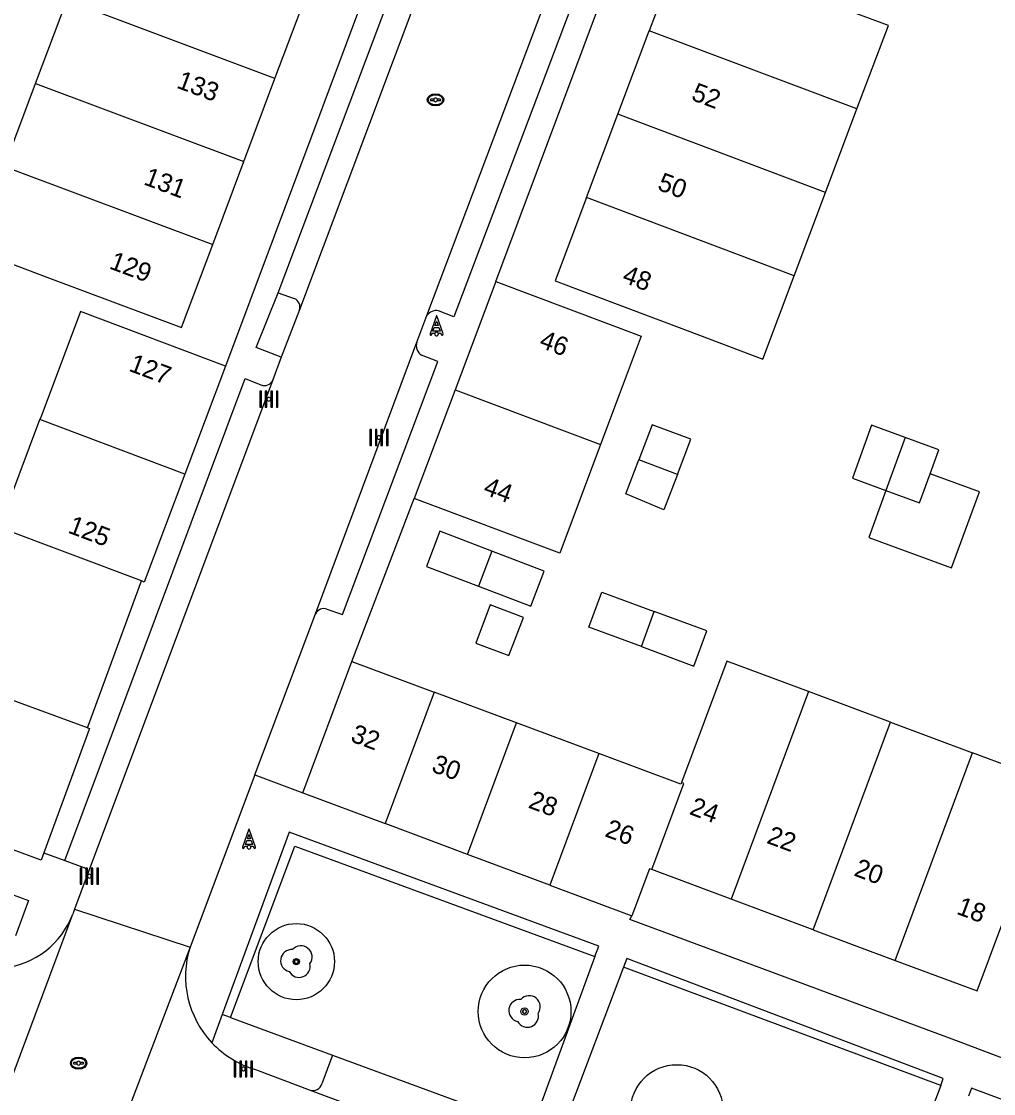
# Model space of a CAD drawing. Extents: x 192664 to 192925, y 446334 to 446521.
# Drawn here: x 192737.6 to 192789.9, y 446395.7 to 446453.5 of the extents above; entities that cross this region are included whole.
import ezdxf

# ---------------------------------------------------------------- set-up
doc = ezdxf.new("R2010")
doc.units = 0
for name, color, linetype in [('( Toegevoegd 29-11-2021 14_41_42) ondersteunend wegdeel vlak', 7, 'Continuous'), ('( Toegevoegd 29-11-2021 14_41_42) wegdeel vlak', 7, 'Continuous'), ('B-GV-GR-BOOM-S', 7, 'Continuous'), ('boom', 7, 'Continuous'), ('bovenleidingmast', 7, 'Continuous'), ('huisnummerreeks BGT', 7, 'Continuous'), ('inspectie-   rioolput', 7, 'Continuous'), ('kant open verharding', 7, 'Continuous'), ('kant verharding', 7, 'Continuous'), ('kolk', 7, 'Continuous'), ('Luifel', 7, 'Continuous'), ('pand op maaiveld vlak', 7, 'Continuous'), ('verkeerseiland - berm', 7, 'Continuous')]:
    doc.layers.add(name, color=color, linetype=linetype)

msp = doc.modelspace()

# ---------------------------------------------------------------- linework, layer by layer
at = {"layer": '( Toegevoegd 29-11-2021 14_41_42) ondersteunend wegdeel vlak'}
for p, q in [((192748.388, 446399.963), (192747.829, 446398.443)), ((192748.841, 446399.796), (192748.388, 446399.963)), ((192754.334, 446397.778), (192753.763, 446396.222)), ((192750.175, 446396.992), (192753.133, 446395.89))]:
    msp.add_line(p, q, dxfattribs=at)
for centre, radius, start, end in [((192751.82, 446402.274), 5.532, 223.8263, 252.70015), ((192753.27, 446396.393), 0.522, 254.72926, 340.84778)]:
    msp.add_arc(centre, radius, start, end, dxfattribs=at)
at = {"layer": '( Toegevoegd 29-11-2021 14_41_42) wegdeel vlak'}
for p, q in [((192750.151, 446412.873), (192746.655, 446403.591)), ((192740.44, 446405.64), (192740.343, 446405.376))]:
    msp.add_line(p, q, dxfattribs=at)
for points in [[(192768.471, 446403.091), (192768.677, 446403.651), (192751.996, 446409.781), (192748.388, 446399.963)], [(192807.071, 446391.618), (192806.989, 446391.38), (192789.199, 446398.084), (192788.212, 446398.449), (192770.35, 446405.075), (192770.467, 446405.283)], [(192787.1, 446396.135), (192787.242, 446396.51), (192770.185, 446402.974), (192770.009, 446402.51)], [(192806.008, 446389.049), (192806.18, 446389.51), (192788.76, 446395.99), (192788.604, 446395.572)]]:
    msp.add_lwpolyline(points, dxfattribs=at)
msp.add_arc((192751.656, 446402.024), 5.241, 162.6006, 223.09258, dxfattribs=at)
at = {"layer": 'B-GV-GR-BOOM-S'}
for centre, radius in [((192752.383, 446402.813), 2.054), ((192752.383, 446402.813), 0.164), ((192764.68, 446400.127), 2.5), ((192764.68, 446400.127), 0.2), ((192772.885, 446394.761), 2.5)]:
    msp.add_circle(centre, radius, dxfattribs=at)
at = {"layer": 'boom'}
for centre in [(192752.383, 446402.813), (192764.68, 446400.127)]:
    msp.add_circle(centre, 0.1, dxfattribs=at)
for centre, radius, start, end in [((192752.633, 446403.063), 0.6, 323.54458, 138.4658), ((192752.133, 446402.863), 0.6, 85.13702, 257.75442), ((192752.533, 446402.563), 0.6, 208.50578, 13.83556), ((192752.383, 446402.813), 0.1, 0, 180), ((192752.383, 446402.813), 0.1, 180, 0), ((192764.43, 446400.177), 0.6, 85.13702, 257.75442), ((192764.93, 446400.377), 0.6, 323.54458, 138.4658), ((192764.68, 446400.127), 0.1, 0, 180), ((192764.68, 446400.127), 0.1, 180, 0), ((192764.83, 446399.877), 0.6, 208.50578, 13.83556)]:
    msp.add_arc(centre, radius, start, end, dxfattribs=at)
at = {"layer": 'bovenleidingmast'}
for p, q in [((192759.928, 446437.605), (192759.587, 446436.632)), ((192760.287, 446436.632), (192759.946, 446437.605)), ((192749.824, 446409.954), (192749.483, 446408.981)), ((192750.183, 446408.981), (192749.842, 446409.954))]:
    msp.add_line(p, q, dxfattribs=at)
for points in [[(192759.946, 446437.302), (192760.024, 446437.082), (192759.85, 446437.082), (192759.928, 446437.302)], [(192759.681, 446436.599), (192759.71, 446436.682), (192759.85, 446436.682)], [(192760.024, 446436.682), (192760.164, 446436.682), (192760.193, 446436.599)], [(192749.842, 446409.651), (192749.92, 446409.431), (192749.746, 446409.431), (192749.824, 446409.651)], [(192749.577, 446408.948), (192749.606, 446409.031), (192749.746, 446409.031)], [(192749.92, 446409.031), (192750.06, 446409.031), (192750.089, 446408.948)]]:
    msp.add_lwpolyline(points, dxfattribs=at)
for points in [[(192760.059, 446436.982), (192760.129, 446436.782), (192759.745, 446436.782), (192759.815, 446436.982)], [(192749.955, 446409.331), (192750.025, 446409.131), (192749.641, 446409.131), (192749.711, 446409.331)]]:
    msp.add_lwpolyline(points, close=True, dxfattribs=at)
for centre, radius, start, end in [((192759.937, 446437.602), 0.01, 19.29005, 160.70995), ((192759.937, 446437.299), 0.01, 19.29005, 160.70995), ((192759.634, 446436.615), 0.05, 160.70995, 340.70995), ((192759.937, 446436.632), 0.1, 0, 180), ((192759.937, 446436.632), 0.1, 180, 0), ((192759.937, 446436.632), 0.1, 30, 150), ((192760.24, 446436.615), 0.05, 199.29005, 19.29005), ((192749.833, 446409.951), 0.01, 19.29005, 160.70995), ((192749.833, 446409.648), 0.01, 19.29005, 160.70995), ((192749.53, 446408.964), 0.05, 160.70995, 340.70995), ((192749.833, 446408.981), 0.1, 0, 180), ((192749.833, 446408.981), 0.1, 180, 0), ((192749.833, 446408.981), 0.1, 30, 150), ((192750.136, 446408.964), 0.05, 199.29005, 19.29005)]:
    msp.add_arc(centre, radius, start, end, dxfattribs=at)
at = {"layer": 'inspectie-   rioolput'}
for p, q in [((192759.79, 446449.284), (192759.633, 446449.284)), ((192759.633, 446449.209), (192759.79, 446449.209)), ((192760.133, 446449.284), (192759.976, 446449.284)), ((192759.976, 446449.209), (192760.133, 446449.209)), ((192740.56, 446397.379), (192740.403, 446397.379)), ((192740.403, 446397.305), (192740.56, 446397.305)), ((192740.903, 446397.379), (192740.746, 446397.379)), ((192740.746, 446397.305), (192740.903, 446397.305))]:
    msp.add_line(p, q, dxfattribs=at)
for centre, radius, start, end in [((192759.633, 446449.246), 0.0375, 90, 270), ((192759.883, 446449.246), 0.1, 0, 180), ((192759.883, 446449.246), 0.1, 157.97569, 180), ((192759.883, 446449.246), 0.1, 180, 202.02431), ((192759.883, 446449.246), 0.1, 180, 0), ((192759.883, 446449.246), 0.1, 0, 22.02431), ((192759.883, 446449.246), 0.1, 337.97569, 0), ((192760.133, 446449.246), 0.0375, 270, 90), ((192740.403, 446397.342), 0.0375, 90, 270), ((192740.653, 446397.342), 0.1, 0, 180), ((192740.653, 446397.342), 0.1, 157.97569, 180), ((192740.653, 446397.342), 0.1, 180, 202.02431), ((192740.653, 446397.342), 0.1, 180, 0), ((192740.653, 446397.342), 0.1, 0, 22.02431), ((192740.653, 446397.342), 0.1, 337.97569, 0), ((192740.903, 446397.342), 0.0375, 270, 90)]:
    msp.add_arc(centre, radius, start, end, dxfattribs=at)
for centre, major_axis, ratio in [((192759.883, 446449.246), (-0.442, 0), 0.73911), ((192759.883, 446449.246), (-0.392, 0), 0.689655), ((192740.653, 446397.342), (-0.442, 0), 0.73911), ((192740.653, 446397.342), (-0.392, 0), 0.689655)]:
    msp.add_ellipse(centre, major_axis=major_axis, ratio=ratio, dxfattribs=at)
at = {"layer": 'kant open verharding'}
for p, q in [((192741.127, 446415.414), (192744.037, 446423.324)), ((192750.151, 446412.873), (192752.736, 446411.901)), ((192738.776, 446408.675), (192739.919, 446408.255))]:
    msp.add_line(p, q, dxfattribs=at)
for points in [[(192759.131, 446463.938), (192758.744, 446462.881), (192758.998, 446462.784), (192748.571, 446434.902)], [(192763.131, 446439.452), (192770.245, 446458.483), (192770.698, 446459.694), (192771.023, 446459.551)], [(192751.571, 446435.377), (192750.222, 446435.901), (192751.413, 446438.852)], [(192755.381, 446418.987), (192758.122, 446426.164), (192758.321, 446426.684), (192758.739, 446427.776)]]:
    msp.add_lwpolyline(points, dxfattribs=at)
msp.add_arc((192736.087, 446407.003), 4.557, 276.55625, 339.08322, dxfattribs=at)
at = {"layer": 'kant verharding'}
for p, q in [((192759.42, 446437.63), (192767.733, 446459.699)), ((192751.413, 446438.852), (192759.133, 446459.368)), ((192760.585, 446459.343), (192752.554, 446437.93)), ((192751.413, 446438.852), (192752.271, 446438.544)), ((192752.554, 446437.93), (192751.571, 446435.377)), ((192758.883, 446436.192), (192759.42, 446437.63)), ((192753.421, 446421.556), (192758.883, 446436.192)), ((192751.571, 446435.377), (192751.119, 446434.16)), ((192751.119, 446434.16), (192741.115, 446407.463)), ((192750.151, 446412.873), (192753.421, 446421.556)), ((192739.919, 446408.255), (192740.927, 446407.876)), ((192741.115, 446407.463), (192740.44, 446405.64)), ((192735.54, 446392.53), (192740.343, 446405.376)), ((192740.44, 446405.64), (192746.655, 446403.591)), ((192746.655, 446403.591), (192741.229, 446389.304)), ((192753.133, 446395.89), (192813.567, 446373.412))]:
    msp.add_line(p, q, dxfattribs=at)
for points in [[(192768.035, 446459.06), (192768.878, 446458.723), (192760.872, 446437.554), (192760.052, 446437.884)], [(192754.031, 446421.809), (192754.871, 446421.511), (192760.002, 446435.156), (192759.135, 446435.492)], [(192739.919, 446408.255), (192749.62, 446434.241), (192750.477, 446433.889)]]:
    msp.add_lwpolyline(points, dxfattribs=at)
for centre, radius, start, end in [((192752.081, 446438.084), 0.498, 341.95105, 67.54004), ((192759.941, 446437.247), 0.647, 80.11998, 143.67028), ((192759.425, 446435.992), 0.578, 159.72169, 239.87607), ((192750.665, 446434.34), 0.489, 247.39333, 338.37767), ((192753.87, 446421.334), 0.501, 71.31361, 153.73925), ((192740.812, 446407.575), 0.322, 339.76342, 69.18719)]:
    msp.add_arc(centre, radius, start, end, dxfattribs=at)
at = {"layer": 'kolk'}
for points in [[(192750.498, 446433.118), (192750.498, 446433.543), (192750.413, 446433.543), (192750.413, 446433.118), (192750.413, 446432.693), (192750.498, 446432.693)], [(192750.796, 446433.118), (192750.796, 446433.543), (192750.711, 446433.543), (192750.711, 446433.118), (192750.711, 446432.693), (192750.796, 446432.693)], [(192751.093, 446433.118), (192751.093, 446433.543), (192751.008, 446433.543), (192751.008, 446433.118), (192751.008, 446432.693), (192751.093, 446432.693)], [(192751.391, 446433.118), (192751.391, 446433.543), (192751.306, 446433.543), (192751.306, 446433.118), (192751.306, 446432.693), (192751.391, 446432.693)], [(192756.43, 446431.056), (192756.43, 446431.481), (192756.345, 446431.481), (192756.345, 446431.056), (192756.345, 446430.631), (192756.43, 446430.631)], [(192756.728, 446431.056), (192756.728, 446431.481), (192756.643, 446431.481), (192756.643, 446431.056), (192756.643, 446430.631), (192756.728, 446430.631)], [(192757.025, 446431.056), (192757.025, 446431.481), (192756.94, 446431.481), (192756.94, 446431.056), (192756.94, 446430.631), (192757.025, 446430.631)], [(192757.323, 446431.056), (192757.323, 446431.481), (192757.238, 446431.481), (192757.238, 446431.056), (192757.238, 446430.631), (192757.323, 446430.631)], [(192740.828, 446407.418), (192740.828, 446407.843), (192740.743, 446407.843), (192740.743, 446407.418), (192740.743, 446406.993), (192740.828, 446406.993)], [(192741.126, 446407.418), (192741.126, 446407.843), (192741.041, 446407.843), (192741.041, 446407.418), (192741.041, 446406.993), (192741.126, 446406.993)], [(192741.423, 446407.418), (192741.423, 446407.843), (192741.338, 446407.843), (192741.338, 446407.418), (192741.338, 446406.993), (192741.423, 446406.993)], [(192741.721, 446407.418), (192741.721, 446407.843), (192741.636, 446407.843), (192741.636, 446407.418), (192741.636, 446406.993), (192741.721, 446406.993)], [(192749.127, 446397.03), (192749.127, 446397.455), (192749.042, 446397.455), (192749.042, 446397.03), (192749.042, 446396.605), (192749.127, 446396.605)], [(192749.425, 446397.03), (192749.425, 446397.455), (192749.34, 446397.455), (192749.34, 446397.03), (192749.34, 446396.605), (192749.425, 446396.605)], [(192749.722, 446397.03), (192749.722, 446397.455), (192749.637, 446397.455), (192749.637, 446397.03), (192749.637, 446396.605), (192749.722, 446396.605)], [(192750.02, 446397.03), (192750.02, 446397.455), (192749.935, 446397.455), (192749.935, 446397.03), (192749.935, 446396.605), (192750.02, 446396.605)]]:
    msp.add_lwpolyline(points, close=True, dxfattribs=at)
for centre, start, end in [((192750.902, 446433.118), 0, 180), ((192750.902, 446433.118), 180, 0), ((192756.834, 446431.056), 0, 180), ((192756.834, 446431.056), 180, 0), ((192741.232, 446407.418), 0, 180), ((192741.232, 446407.418), 180, 0), ((192749.531, 446397.03), 0, 180), ((192749.531, 446397.03), 180, 0)]:
    msp.add_arc(centre, 0.1, start, end, dxfattribs=at)
at = {"layer": 'Luifel'}
msp.add_lwpolyline([(192784.152, 446428.199), (192783.226, 446425.665), (192787.691, 446424.032), (192789.19, 446428.134), (192786.534, 446429.105)], dxfattribs=at)
at = {"layer": 'pand op maaiveld vlak'}
for p, q in [((192738.338, 446450.129), (192740.015, 446454.605)), ((192751.233, 446450.4), (192740.015, 446454.605)), ((192751.233, 446450.4), (192752.91, 446454.875)), ((192769.708, 446448.482), (192771.4, 446452.974)), ((192782.591, 446448.755), (192771.4, 446452.974)), ((192749.556, 446445.924), (192751.233, 446450.4)), ((192736.66, 446445.654), (192738.338, 446450.129)), ((192738.338, 446450.129), (192749.556, 446445.924)), ((192780.892, 446444.248), (192782.591, 446448.755)), ((192768.015, 446443.99), (192769.708, 446448.482)), ((192780.892, 446444.248), (192769.708, 446448.482)), ((192747.878, 446441.449), (192749.556, 446445.924)), ((192736.66, 446445.654), (192747.878, 446441.449)), ((192779.205, 446439.772), (192768.015, 446443.99)), ((192779.205, 446439.772), (192780.892, 446444.248)), ((192763.131, 446439.452), (192760.935, 446433.614)), ((192748.571, 446434.902), (192746.38, 446429.084)), ((192760.935, 446433.614), (192758.739, 446427.776)), ((192760.935, 446433.614), (192768.768, 446430.668)), ((192746.38, 446429.084), (192738.567, 446432.027)), ((192785.188, 446431.059), (192784.152, 446428.199)), ((192772.913, 446429.063), (192770.835, 446429.846)), ((192762.92, 446424.928), (192762.202, 446423.04)), ((192770.972, 446419.787), (192771.672, 446421.682)), ((192752.736, 446411.901), (192755.381, 446418.987)), ((192755.381, 446418.987), (192759.813, 446417.332)), ((192741.127, 446415.414), (192736.734, 446417.029)), ((192759.813, 446417.332), (192757.169, 446410.247)), ((192764.246, 446415.677), (192759.813, 446417.332)), ((192779.986, 446417.36), (192775.811, 446406.179)), ((192784.402, 446415.712), (192779.986, 446417.36)), ((192761.602, 446408.592), (192764.246, 446415.677)), ((192768.678, 446414.021), (192764.246, 446415.677)), ((192780.227, 446404.53), (192784.402, 446415.712)), ((192784.402, 446415.712), (192788.818, 446414.063)), ((192768.678, 446414.021), (192766.034, 446406.937)), ((192784.643, 446402.882), (192788.818, 446414.063)), ((192752.736, 446411.901), (192757.169, 446410.247)), ((192761.602, 446408.592), (192757.169, 446410.247)), ((192766.034, 446406.937), (192761.602, 446408.592)), ((192775.811, 446406.179), (192771.535, 446407.775)), ((192766.034, 446406.937), (192770.467, 446405.283)), ((192780.227, 446404.53), (192775.811, 446406.179)), ((192780.227, 446404.53), (192784.643, 446402.882))]:
    msp.add_line(p, q, dxfattribs=at)
for points in [[(192782.591, 446448.755), (192784.284, 446453.247), (192780.202, 446454.786), (192773.094, 446457.465), (192771.4, 446452.974)], [(192736.66, 446445.654), (192734.983, 446441.178), (192739.086, 446439.641), (192746.201, 446436.974), (192747.878, 446441.449)], [(192768.015, 446443.99), (192766.321, 446439.499), (192773.437, 446436.816), (192777.512, 446435.28), (192779.205, 446439.772)], [(192763.131, 446439.452), (192770.966, 446436.505), (192769.779, 446433.348), (192768.768, 446430.668)], [(192748.571, 446434.902), (192740.758, 446437.844), (192738.627, 446432.186), (192738.567, 446432.027)], [(192744.037, 446423.324), (192736.376, 446426.21), (192738.567, 446432.027)], [(192772.913, 446429.063), (192773.633, 446430.966), (192771.564, 446431.745), (192770.835, 446429.846)], [(192785.188, 446431.059), (192783.371, 446431.724), (192782.345, 446428.861), (192784.152, 446428.199)], [(192768.768, 446430.668), (192766.573, 446424.829), (192758.739, 446427.776)], [(192786.534, 446429.105), (192787.005, 446430.394), (192785.188, 446431.059)], [(192772.913, 446429.063), (192772.193, 446427.16), (192770.135, 446428.024), (192770.835, 446429.846)], [(192746.38, 446429.084), (192744.189, 446423.267), (192744.037, 446423.324)], [(192784.152, 446428.199), (192785.96, 446427.538), (192786.534, 446429.105)], [(192762.92, 446424.928), (192760.107, 446426), (192759.389, 446424.112), (192762.202, 446423.04)], [(192762.202, 446423.04), (192765.014, 446421.968), (192765.732, 446423.856), (192762.92, 446424.928)], [(192770.972, 446419.787), (192768.149, 446420.832), (192768.849, 446422.727), (192771.672, 446421.682)], [(192763.839, 446419.299), (192764.616, 446421.364), (192762.822, 446422.039), (192762.046, 446419.973), (192763.839, 446419.299)], [(192770.972, 446419.787), (192773.794, 446418.741), (192774.494, 446420.636), (192771.672, 446421.682)], [(192779.986, 446417.36), (192775.57, 446419.009), (192773.128, 446412.468)], [(192741.127, 446415.414), (192741.237, 446415.373), (192738.776, 446408.675)], [(192773.128, 446412.468), (192773.093, 446412.373), (192768.678, 446414.021)], [(192784.643, 446402.882), (192789.06, 446401.234), (192791.717, 446408.352), (192793.234, 446412.413), (192788.818, 446414.063)], [(192771.535, 446407.775), (192773.267, 446412.416), (192773.128, 446412.468)], [(192738.776, 446408.675), (192738.63, 446408.277), (192734.126, 446409.932)], [(192771.535, 446407.775), (192771.414, 446407.82), (192770.467, 446405.283)]]:
    msp.add_lwpolyline(points, dxfattribs=at)
at = {"layer": 'verkeerseiland - berm'}
for p, q in [((192768.471, 446403.091), (192765.07, 446393.833)), ((192770.009, 446402.51), (192766.521, 446393.307)), ((192787.1, 446396.135), (192770.009, 446402.51)), ((192748.841, 446399.796), (192754.334, 446397.778)), ((192754.334, 446397.778), (192765.07, 446393.833)), ((192787.1, 446396.135), (192783.608, 446386.92))]:
    msp.add_line(p, q, dxfattribs=at)
for points in [[(192748.841, 446399.796), (192752.303, 446409.032), (192768.471, 446403.091)], [(192731.902, 446406.177), (192732.604, 446408.083), (192737.948, 446406.115), (192737.245, 446404.209)]]:
    msp.add_lwpolyline(points, dxfattribs=at)

# ---------------------------------------------------------------- texts
at = {"layer": 'huisnummerreeks BGT'}
for s, rotation, p in [('133', 339.5, (192745.883, 446449.913)), ('52', 339.4, (192773.608, 446449.262)), ('131', 339.5, (192744.106, 446444.704)), ('50', 339.4, (192771.787, 446444.421)), ('129', 339.5, (192742.253, 446440.175)), ('48', 339.4, (192769.887, 446439.441)), ('46', 339.4, (192765.413, 446435.934)), ('127', 339.4, (192743.306, 446434.658)), ('44', 339.4, (192762.4, 446428.025)), ('125', 339.4, (192740.026, 446425.941)), ('32', 339.6, (192755.251, 446414.698)), ('30', 339.6, (192759.611, 446413.071)), ('28', 339.6, (192764.829, 446411.123)), ('24', 339.6, (192773.511, 446410.773)), ('26', 339.6, (192768.952, 446409.583)), ('22', 339.6, (192777.675, 446409.219)), ('20', 339.6, (192782.378, 446407.463)), ('18', 339.6, (192787.901, 446405.402))]:
    msp.add_text(s, height=1, rotation=rotation, dxfattribs=at).set_placement(p)

doc.saveas('drawing.dxf')
